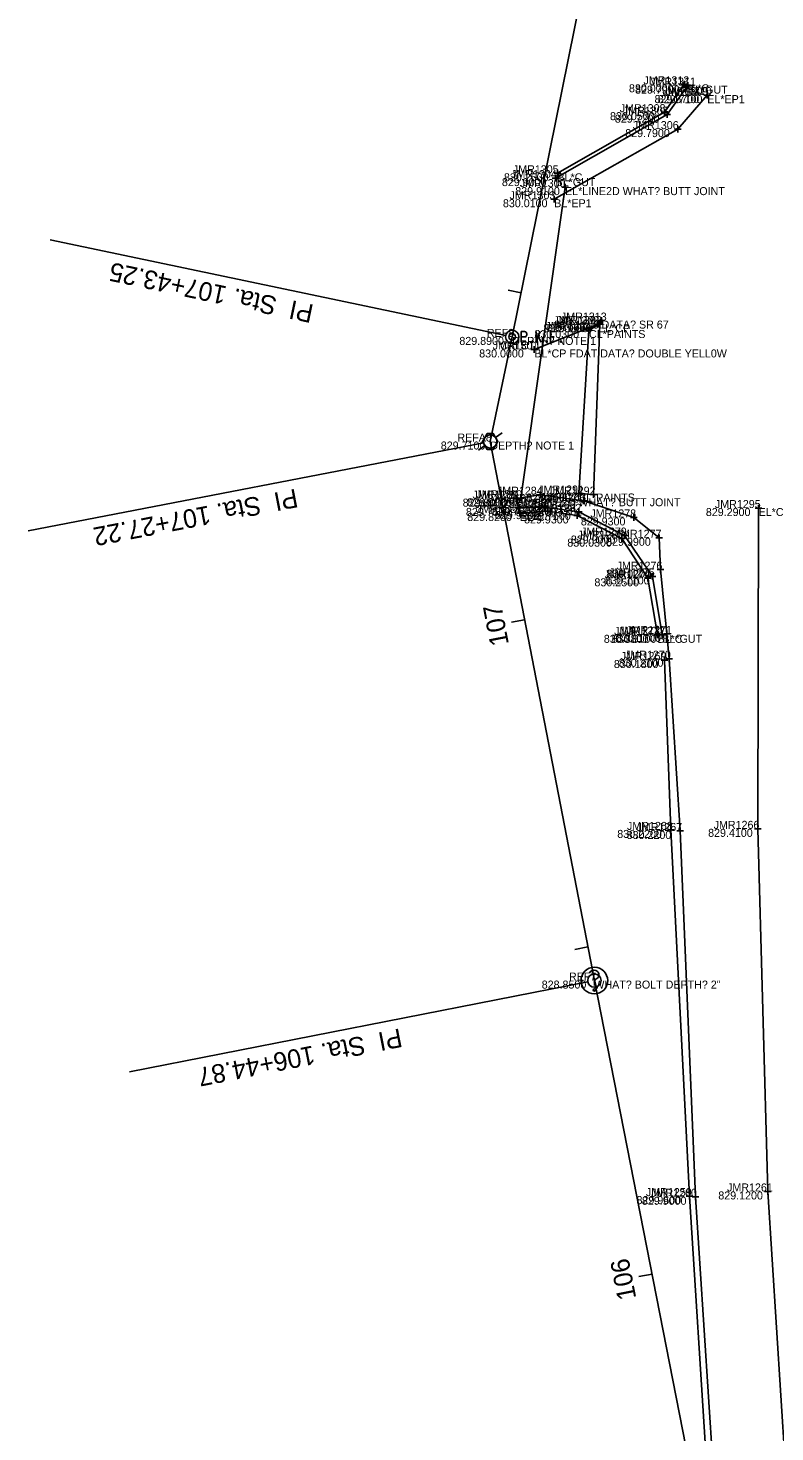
# Model space of a CAD drawing. Extents: x 1800057 to 1804439, y 483822 to 495007.
# Drawn here: x 1800057 to 1800169.1, y 493615 to 493825.6 of the extents above; entities that cross this region are included whole.
import ezdxf

# ---------------------------------------------------------------- set-up
doc = ezdxf.new("R2010")
doc.units = 0
for name, color, linetype in [('Default', 7, 'Continuous'), ('PM_X_Stop_Line', 7, 'Continuous'), ('PV_X_Curb', 7, 'Continuous'), ('PV_X_EOP', 7, 'Continuous'), ('PV_X_Shoulder', 7, 'Continuous'), ('RD_X_Misc_Items', 7, 'Continuous'), ('SV_X_Center_of_Pavt', 7, 'Continuous'), ('SV_X_CL_Survey_20', 7, 'Continuous'), ('SV_X_Control_Cells_Found', 7, 'Continuous'), ('SV_X_Shot_Marker', 7, 'Continuous'), ('SV_X_Text_Comment', 7, 'Continuous'), ('SV_X_Text_Elevation', 7, 'Continuous'), ('SV_X_Text_Name', 7, 'Continuous')]:
    doc.layers.add(name, color=color, linetype=linetype)

msp = doc.modelspace()

# ---------------------------------------------------------------- linework, layer by layer
at = {"layer": 'Default'}
msp.add_line((1800130.91, 493755.03), (1800137.56, 493801.7), dxfattribs=at)
at = {"layer": 'PM_X_Stop_Line'}
msp.add_lwpolyline([(1800139.65, 493755.74), (1800141.82, 493755.57), (1800142.77, 493781.15), (1800141.15, 493780.26), (1800139.65, 493755.74)], dxfattribs=at)
at = {"layer": 'PV_X_Curb'}
for points in [[(1800136.14, 493803.05), (1800152.91, 493812.57), (1800155.99, 493816.92)], [(1800136.42, 493803.77), (1800152.47, 493812.94), (1800155.42, 493817.12)], [(1800152.16, 493734.55), (1800150.67, 493743.31), (1800146.48, 493749.43), (1800139.65, 493752.99), (1800134.5, 493753.68), (1800130.59, 493753.58)], [(1800151.44, 493734.54), (1800150, 493743.02), (1800146.08, 493748.97), (1800139.36, 493752.45), (1800134.96, 493753.1), (1800130.78, 493752.81)]]:
    msp.add_lwpolyline(points, dxfattribs=at)
at = {"layer": 'PV_X_EOP'}
for points in [[(1800135.93, 493799.88), (1800154.5, 493810.4), (1800158.9, 493815.49)], [(1800458.51, 492019.19), (1800428.97, 492172.53), (1800371.73, 492460.04), (1800290.68, 492869.75), (1800235.42, 493149.26), (1800191.6, 493379.4), (1800183.7, 493423.96), (1800176.66, 493466.11), (1800169.82, 493511.65), (1800164.64, 493555.78), (1800160.38, 493600.77), (1800157.14, 493650.25), (1800154.83, 493705.12), (1800153.18, 493730.96), (1800152.82, 493734.69), (1800151.9, 493744.32), (1800151.68, 493749.1), (1800147.88, 493752.15), (1800140.39, 493754.62), (1800133.87, 493755.56), (1800130.23, 493754.97)]]:
    msp.add_lwpolyline(points, dxfattribs=at)
at = {"layer": 'PV_X_Shoulder'}
msp.add_lwpolyline([(1800457.45, 492018.92), (1800428.43, 492172.5), (1800370.8, 492459.92), (1800289.79, 492869.77), (1800234.57, 493149.05), (1800190.93, 493379.44), (1800182.91, 493423.69), (1800175.76, 493466.05), (1800168.8, 493511.21), (1800163.57, 493555.93), (1800159.41, 493600.52), (1800156.25, 493650.35), (1800153.42, 493705.28), (1800152.47, 493730.76)], dxfattribs=at)
at = {"layer": 'RD_X_Misc_Items'}
msp.add_line((1800141.96, 493681.92), (1800141.96, 493682.4), dxfattribs=at)
for centre, radius in [((1800141.96, 493682.68), 2), ((1800141.96, 493681.27), 0.17)]:
    msp.add_circle(centre, radius, dxfattribs=at)
for centre, radius, start, end in [((1800141.89, 493683.49), 0.754, 88.324, 152.5385), ((1800141.95, 493683.56), 0.688, 291.9329, 92.4584), ((1800142.54, 493682.44), 0.587, 125.4618, 184.0829)]:
    msp.add_arc(centre, radius, start, end, dxfattribs=at)
at = {"layer": 'SV_X_Center_of_Pavt'}
msp.add_line((1800132.95, 493777.35), (1800142.51, 493781.14), dxfattribs=at)
msp.add_lwpolyline([(1800469.01, 492021.22), (1800439.37, 492174.81), (1800382.15, 492462.11), (1800301, 492872.15), (1800245.93, 493151.03), (1800202.07, 493381.28), (1800193.97, 493425.46), (1800186.87, 493467.92), (1800180.32, 493514.37), (1800175.39, 493555.88), (1800171.19, 493600.63), (1800167.99, 493651.05), (1800166.49, 493705.44), (1800166.61, 493753.56)], dxfattribs=at)
at = {"layer": 'SV_X_CL_Survey_20'}
for p, q in [((1800129.64, 493779.23), (1800291.16, 494582.06)), ((1800129.64, 493779.23), (1800291.16, 494582.06)), ((1800128.66, 493779.43), (1800060.32, 493793.81)), ((1800130.97, 493785.84), (1800129.01, 493786.24)), ((1800126.34, 493763.54), (1800129.64, 493779.23)), ((1800126.34, 493763.54), (1800129.64, 493779.23)), ((1800125.36, 493763.35), (1800056.98, 493750.15)), ((1800141.96, 493682.68), (1800126.34, 493763.54)), ((1800141.96, 493682.68), (1800126.34, 493763.54)), ((1800131.5, 493736.81), (1800129.54, 493736.43)), ((1800140.98, 493687.72), (1800139.02, 493687.34)), ((1800140.98, 493682.49), (1800072.21, 493668.97)), ((1800325.88, 492747.04), (1800141.96, 493682.68)), ((1800325.88, 492747.04), (1800141.96, 493682.68)), ((1800150.61, 493638.66), (1800148.65, 493638.27))]:
    msp.add_line(p, q, dxfattribs=at)
for centre in [(1800129.64, 493779.23), (1800126.34, 493763.54), (1800141.96, 493682.68)]:
    msp.add_circle(centre, 1, dxfattribs=at)
at = {"layer": 'SV_X_Control_Cells_Found'}
for p, q in [((1800128.11, 493764.86), (1800127.14, 493764.14)), ((1800125.53, 493762.94), (1800124.57, 493762.22))]:
    msp.add_line(p, q, dxfattribs=at)
for points in [[(1800131, 493778.43), (1800131, 493780.03), (1800131.53, 493780.03), (1800131.58, 493780.01), (1800131.66, 493779.99), (1800131.69, 493779.96), (1800131.73, 493779.94), (1800131.77, 493779.87), (1800131.8, 493779.81), (1800131.83, 493779.71), (1800131.83, 493779.56), (1800131.81, 493779.51), (1800131.79, 493779.43), (1800131.75, 493779.34), (1800131.7, 493779.31), (1800131.67, 493779.28), (1800131.62, 493779.26), (1800131.53, 493779.24), (1800131, 493779.24)], [(1800132.64, 493778.64), (1800132.7, 493778.64), (1800132.73, 493778.61), (1800132.76, 493778.56), (1800132.76, 493778.5), (1800132.73, 493778.45), (1800132.7, 493778.43), (1800132.64, 493778.43), (1800132.61, 493778.45), (1800132.58, 493778.5), (1800132.58, 493778.56), (1800132.61, 493778.61), (1800132.64, 493778.64)], [(1800133.25, 493780.03), (1800133.25, 493778.43)], [(1800133.89, 493780.03), (1800133.25, 493779)], [(1800133.46, 493779.33), (1800134, 493778.43)], [(1800134.78, 493778.64), (1800134.84, 493778.64), (1800134.87, 493778.61), (1800134.9, 493778.56), (1800134.9, 493778.5), (1800134.87, 493778.45), (1800134.84, 493778.43), (1800134.78, 493778.43), (1800134.75, 493778.45), (1800134.71, 493778.5), (1800134.71, 493778.56), (1800134.75, 493778.61), (1800134.78, 493778.64)], [(1800136.15, 493780.03), (1800135.39, 493780.03), (1800135.39, 493778.43)], [(1800135.39, 493779.24), (1800135.93, 493779.24)], [(1800136.93, 493778.64), (1800136.98, 493778.64), (1800137.02, 493778.61), (1800137.05, 493778.56), (1800137.05, 493778.5), (1800137.02, 493778.45), (1800136.98, 493778.43), (1800136.93, 493778.43), (1800136.9, 493778.45), (1800136.86, 493778.5), (1800136.86, 493778.56), (1800136.9, 493778.61), (1800136.93, 493778.64)]]:
    msp.add_lwpolyline(points, dxfattribs=at)
msp.add_lwpolyline([(1800125.89, 493764.74), (1800126.79, 493764.74), (1800127.5, 493763.54), (1800126.79, 493762.34), (1800125.89, 493762.34), (1800125.18, 493763.54)], close=True, dxfattribs=at)
msp.add_circle((1800129.64, 493779.23), 0.497, dxfattribs=at)
at = {"layer": 'SV_X_Shot_Marker'}
for p, q in [((1800154.92, 493817.12), (1800155.92, 493817.12)), ((1800155.42, 493817.62), (1800155.42, 493816.62)), ((1800155.42, 493817.12), (1800155.42, 493817.12)), ((1800155.49, 493816.92), (1800156.49, 493816.92)), ((1800155.99, 493817.42), (1800155.99, 493816.42)), ((1800155.99, 493816.92), (1800155.99, 493816.92)), ((1800158.9, 493815.99), (1800158.9, 493814.99)), ((1800158.91, 493816), (1800158.91, 493815)), ((1800158.4, 493815.49), (1800159.4, 493815.49)), ((1800158.41, 493815.5), (1800159.41, 493815.5)), ((1800158.9, 493815.49), (1800158.9, 493815.49)), ((1800158.91, 493815.5), (1800158.91, 493815.5)), ((1800151.97, 493812.94), (1800152.97, 493812.94)), ((1800152.41, 493812.57), (1800153.41, 493812.57)), ((1800152.47, 493813.44), (1800152.47, 493812.44)), ((1800152.47, 493812.94), (1800152.47, 493812.94)), ((1800152.91, 493813.07), (1800152.91, 493812.07)), ((1800152.91, 493812.57), (1800152.91, 493812.57)), ((1800154, 493810.4), (1800155, 493810.4)), ((1800154.5, 493810.9), (1800154.5, 493809.9)), ((1800154.5, 493810.4), (1800154.5, 493810.4)), ((1800135.92, 493803.77), (1800136.92, 493803.77)), ((1800136.14, 493803.55), (1800136.14, 493802.55)), ((1800136.42, 493804.27), (1800136.42, 493803.27)), ((1800136.42, 493803.77), (1800136.42, 493803.77)), ((1800135.64, 493803.05), (1800136.64, 493803.05)), ((1800136.14, 493803.05), (1800136.14, 493803.05)), ((1800137.06, 493801.7), (1800138.06, 493801.7)), ((1800137.56, 493802.2), (1800137.56, 493801.2)), ((1800137.56, 493801.7), (1800137.56, 493801.7)), ((1800135.43, 493799.88), (1800136.43, 493799.88)), ((1800135.93, 493800.38), (1800135.93, 493799.38)), ((1800135.93, 493799.88), (1800135.93, 493799.88)), ((1800140.65, 493780.26), (1800141.65, 493780.26)), ((1800141.15, 493780.76), (1800141.15, 493779.76)), ((1800141.15, 493780.26), (1800141.15, 493780.26)), ((1800142.01, 493781.14), (1800143.01, 493781.14)), ((1800142.27, 493781.15), (1800143.27, 493781.15)), ((1800142.51, 493781.64), (1800142.51, 493780.64)), ((1800142.51, 493781.14), (1800142.51, 493781.14)), ((1800142.54, 493781.68), (1800143.54, 493781.68)), ((1800142.77, 493781.65), (1800142.77, 493780.65)), ((1800142.77, 493781.15), (1800142.77, 493781.15)), ((1800143.04, 493782.18), (1800143.04, 493781.18)), ((1800143.04, 493781.68), (1800143.04, 493781.68)), ((1800132.45, 493777.35), (1800133.45, 493777.35)), ((1800132.45, 493777.35), (1800133.45, 493777.35)), ((1800132.95, 493777.85), (1800132.95, 493776.85)), ((1800132.95, 493777.85), (1800132.95, 493776.85)), ((1800132.95, 493777.35), (1800132.95, 493777.35)), ((1800132.95, 493777.35), (1800132.95, 493777.35)), ((1800129.73, 493754.97), (1800130.73, 493754.97)), ((1800130.23, 493755.47), (1800130.23, 493754.47)), ((1800130.23, 493754.97), (1800130.23, 493754.97)), ((1800130.41, 493755.03), (1800131.41, 493755.03)), ((1800130.91, 493755.53), (1800130.91, 493754.53)), ((1800130.91, 493755.03), (1800130.91, 493755.03)), ((1800133.37, 493755.56), (1800134.37, 493755.56)), ((1800133.87, 493756.06), (1800133.87, 493755.06)), ((1800133.87, 493755.56), (1800133.87, 493755.56)), ((1800139.15, 493755.74), (1800140.15, 493755.74)), ((1800139.65, 493756.24), (1800139.65, 493755.24)), ((1800139.65, 493755.74), (1800139.65, 493755.74)), ((1800140.39, 493755.12), (1800140.39, 493754.12)), ((1800141.32, 493755.57), (1800142.32, 493755.57)), ((1800141.82, 493756.07), (1800141.82, 493755.07)), ((1800141.82, 493755.57), (1800141.82, 493755.57)), ((1800130.09, 493753.58), (1800131.09, 493753.58)), ((1800130.28, 493752.81), (1800131.28, 493752.81)), ((1800130.59, 493754.08), (1800130.59, 493753.08)), ((1800130.59, 493753.58), (1800130.59, 493753.58)), ((1800130.78, 493753.31), (1800130.78, 493752.31)), ((1800130.78, 493752.81), (1800130.78, 493752.81)), ((1800134, 493753.68), (1800135, 493753.68)), ((1800134.46, 493753.1), (1800135.46, 493753.1)), ((1800134.5, 493754.18), (1800134.5, 493753.18)), ((1800134.5, 493753.68), (1800134.5, 493753.68)), ((1800134.96, 493753.6), (1800134.96, 493752.6)), ((1800134.96, 493753.1), (1800134.96, 493753.1)), ((1800139.15, 493752.99), (1800140.15, 493752.99)), ((1800139.36, 493752.95), (1800139.36, 493751.95)), ((1800139.65, 493753.49), (1800139.65, 493752.49)), ((1800139.65, 493752.99), (1800139.65, 493752.99)), ((1800139.89, 493754.62), (1800140.89, 493754.62)), ((1800140.39, 493754.62), (1800140.39, 493754.62)), ((1800166.11, 493753.56), (1800167.11, 493753.56)), ((1800166.61, 493754.06), (1800166.61, 493753.06)), ((1800166.61, 493753.56), (1800166.61, 493753.56)), ((1800138.86, 493752.45), (1800139.86, 493752.45)), ((1800139.36, 493752.45), (1800139.36, 493752.45)), ((1800147.38, 493752.15), (1800148.38, 493752.15)), ((1800147.88, 493752.65), (1800147.88, 493751.65)), ((1800147.88, 493752.15), (1800147.88, 493752.15)), ((1800145.58, 493748.97), (1800146.58, 493748.97)), ((1800145.98, 493749.43), (1800146.98, 493749.43)), ((1800146.08, 493749.47), (1800146.08, 493748.47)), ((1800146.08, 493748.97), (1800146.08, 493748.97)), ((1800146.48, 493749.93), (1800146.48, 493748.93)), ((1800146.48, 493749.43), (1800146.48, 493749.43)), ((1800151.18, 493749.1), (1800152.18, 493749.1)), ((1800151.68, 493749.6), (1800151.68, 493748.6)), ((1800151.68, 493749.1), (1800151.68, 493749.1)), ((1800151.9, 493744.82), (1800151.9, 493743.82)), ((1800149.5, 493743.02), (1800150.5, 493743.02)), ((1800150, 493743.52), (1800150, 493742.52)), ((1800150, 493743.02), (1800150, 493743.02)), ((1800150.17, 493743.31), (1800151.17, 493743.31)), ((1800150.67, 493743.81), (1800150.67, 493742.81)), ((1800150.67, 493743.31), (1800150.67, 493743.31)), ((1800151.4, 493744.32), (1800152.4, 493744.32)), ((1800151.9, 493744.32), (1800151.9, 493744.32)), ((1800150.94, 493734.54), (1800151.94, 493734.54)), ((1800151.44, 493735.04), (1800151.44, 493734.04)), ((1800151.44, 493734.54), (1800151.44, 493734.54)), ((1800151.66, 493734.55), (1800152.66, 493734.55)), ((1800152.16, 493735.05), (1800152.16, 493734.05)), ((1800152.16, 493734.55), (1800152.16, 493734.55)), ((1800152.32, 493734.69), (1800153.32, 493734.69)), ((1800152.82, 493735.19), (1800152.82, 493734.19)), ((1800152.82, 493734.69), (1800152.82, 493734.69)), ((1800151.97, 493730.76), (1800152.97, 493730.76)), ((1800152.47, 493731.26), (1800152.47, 493730.26)), ((1800152.47, 493730.76), (1800152.47, 493730.76)), ((1800152.68, 493730.96), (1800153.68, 493730.96)), ((1800153.18, 493731.46), (1800153.18, 493730.46)), ((1800153.18, 493730.96), (1800153.18, 493730.96)), ((1800152.92, 493705.28), (1800153.92, 493705.28)), ((1800153.42, 493705.78), (1800153.42, 493704.78)), ((1800153.42, 493705.28), (1800153.42, 493705.28)), ((1800154.33, 493705.12), (1800155.33, 493705.12)), ((1800154.83, 493705.62), (1800154.83, 493704.62)), ((1800154.83, 493705.12), (1800154.83, 493705.12)), ((1800165.99, 493705.44), (1800166.99, 493705.44)), ((1800166.49, 493705.94), (1800166.49, 493704.94)), ((1800166.49, 493705.44), (1800166.49, 493705.44)), ((1800155.75, 493650.35), (1800156.75, 493650.35)), ((1800156.25, 493650.85), (1800156.25, 493649.85)), ((1800156.25, 493650.35), (1800156.25, 493650.35)), ((1800156.64, 493650.25), (1800157.64, 493650.25)), ((1800157.14, 493650.75), (1800157.14, 493649.75)), ((1800157.14, 493650.25), (1800157.14, 493650.25)), ((1800167.49, 493651.05), (1800168.49, 493651.05)), ((1800167.99, 493651.55), (1800167.99, 493650.55)), ((1800167.99, 493651.05), (1800167.99, 493651.05))]:
    msp.add_line(p, q, dxfattribs=at)

# ---------------------------------------------------------------- texts
at = {"layer": 'SV_X_CL_Survey_20'}
for s, rotation, p in [('PI  Sta. 107+43.25', 168.1206, (1800099.99, 493784.03)), ('PI  Sta. 107+27.22', 190.9321, (1800097.15, 493756.48)), ('107', 100.9321, (1800129.15, 493733.16)), ('PI  Sta. 106+44.87', 191.1211, (1800112.79, 493675.52)), ('106', 101.1211, (1800148.26, 493635.05))]:
    msp.add_text(s, height=2.8, rotation=rotation, dxfattribs=at).set_placement(p)
at = {"layer": 'SV_X_Text_Comment'}
for s, p in [('EL*C', (1800155.42, 493815.92)), ('EL*GUT', (1800155.99, 493815.72)), ('EL*EP1', (1800158.9, 493814.29)), ('EL*EP1', (1800158.91, 493814.3)), ('BL*C', (1800136.42, 493802.57)), ('BL*GUT', (1800136.14, 493801.85)), ('EL*LINE2D WHAT? BUTT JOINT', (1800137.56, 493800.5)), ('BL*EP1', (1800135.93, 493798.68)), ('CL*PAINTS', (1800141.15, 493779.06)), ('EL*CP', (1800142.51, 493779.94)), ('DATA? SR 67', (1800143.04, 493780.48)), ('DEPTH? NOTE 1', (1800129.64, 493778.03)), ('BL*CP FDAT DATA? DOUBLE YELL0W', (1800132.95, 493776.15)), ('DEPTH? NOTE 1', (1800126.34, 493762.34)), ('EL*EP1', (1800130.23, 493753.77)), ('BL*LINE2D WHAT? BUTT JOINT', (1800130.91, 493753.83)), ('BL*PAINTS', (1800139.65, 493754.54)), ('EL*GUT', (1800130.59, 493752.38)), ('EL*C', (1800130.78, 493751.61)), ('EL*CP', (1800166.61, 493752.36)), ('BL*C', (1800151.44, 493733.34)), ('BL*GUT', (1800152.16, 493733.35)), ('WHAT? BOLT DEPTH? 2"', (1800141.96, 493681.48))]:
    msp.add_text(s, height=1.2, dxfattribs=at).set_placement(p)
at = {"layer": 'SV_X_Text_Elevation'}
for s, p in [('830.0000', (1800147.15, 493815.92)), ('829.7900', (1800148.07, 493815.72)), ('829.6700', (1800150.99, 493814.3)), ('829.7100', (1800151.48, 493814.29)), ('830.0500', (1800144.31, 493811.74)), ('829.7200', (1800145.03, 493811.37)), ('829.7900', (1800146.59, 493809.2)), ('830.2500', (1800128.39, 493802.57)), ('829.9000', (1800128.09, 493801.85)), ('829.9100', (1800130.09, 493800.5)), ('830.0100', (1800128.24, 493798.68)), ('830.0300', (1800132.97, 493779.06)), ('830.0300', (1800134.32, 493779.94)), ('829.9900', (1800134.82, 493779.95)), ('830.1100', (1800135.94, 493780.48)), ('829.8900', (1800121.7, 493778.03)), ('830.0000', (1800124.68, 493776.15)), ('830.0000', (1800124.68, 493776.15)), ('829.7100', (1800118.91, 493762.34)), ('829.8000', (1800122.2, 493753.77)), ('829.8000', (1800122.88, 493753.83)), ('829.8500', (1800125.95, 493754.36)), ('829.8600', (1800131.71, 493754.54)), ('829.8700', (1800133.92, 493754.37)), ('829.7500', (1800122.69, 493752.38)), ('829.8200', (1800122.89, 493751.61)), ('829.7500', (1800126.61, 493752.48)), ('829.9200', (1800127.04, 493751.9)), ('829.7600', (1800131.73, 493751.79)), ('829.8400', (1800132.47, 493753.42)), ('829.2900', (1800158.69, 493752.36)), ('829.9300', (1800131.41, 493751.25)), ('829.9300', (1800139.93, 493750.95)), ('830.0300', (1800137.9, 493747.77)), ('829.9000', (1800138.43, 493748.23)), ('829.9900', (1800143.73, 493747.9)), ('830.2500', (1800141.97, 493741.82)), ('830.1100', (1800143.56, 493742.11)), ('830.0200', (1800143.75, 493743.12)), ('830.3800', (1800143.38, 493733.34)), ('830.3100', (1800144.56, 493733.35)), ('830.1700', (1800145.26, 493733.49)), ('830.1800', (1800144.89, 493729.56)), ('830.2100', (1800145.63, 493729.76)), ('830.2200', (1800145.4, 493704.08)), ('830.2200', (1800146.81, 493703.92)), ('829.4100', (1800159.03, 493704.24)), ('828.8500', (1800134.06, 493681.48)), ('829.9600', (1800148.29, 493649.15)), ('829.9000', (1800149.09, 493649.05)), ('829.1200', (1800160.56, 493649.85))]:
    msp.add_text(s, height=1.2, dxfattribs=at).set_placement(p)
at = {"layer": 'SV_X_Text_Name'}
for s, p in [('JMR1312', (1800149.33, 493817.12)), ('JMR1311', (1800150.32, 493816.92)), ('JMR1309', (1800152.2, 493815.49)), ('JMR1310', (1800152.7, 493815.5)), ('JMR1308', (1800145.77, 493812.94)), ('JMR1307', (1800146.23, 493812.57)), ('JMR1306', (1800147.74, 493810.4)), ('JMR1304', (1800129.46, 493803.05)), ('JMR1305', (1800129.73, 493803.77)), ('JMR1300', (1800130.77, 493801.7)), ('JMR1303', (1800129.24, 493799.88)), ('JMR1302', (1800135.83, 493781.14)), ('JMR1293', (1800136.22, 493781.15)), ('JMR1313', (1800136.94, 493781.68)), ('REF8', (1800125.82, 493779.23)), ('JMR1294', (1800134.61, 493780.26)), ('JMR1301', (1800126.7, 493777.35)), ('CALC11', (1800127.82, 493777.35)), ('REFA8', (1800121.4, 493763.54)), ('JMR1289', (1800123.69, 493754.97)), ('JMR1290', (1800124.25, 493755.03)), ('JMR1284', (1800127.34, 493755.56)), ('JMR1291', (1800133.53, 493755.74)), ('JMR1283', (1800133.85, 493754.62)), ('JMR1292', (1800135.27, 493755.57)), ('JMR1288', (1800124.05, 493753.58)), ('JMR1287', (1800124.25, 493752.81)), ('JMR1285', (1800127.97, 493753.68)), ('JMR1286', (1800128.35, 493753.1)), ('JMR1282', (1800133.12, 493752.99)), ('JMR1281', (1800133.26, 493752.45)), ('JMR1278', (1800141.36, 493752.15)), ('JMR1295', (1800160.05, 493753.56)), ('JMR1280', (1800139.44, 493748.97)), ('JMR1279', (1800139.95, 493749.43)), ('JMR1277', (1800145.16, 493749.1)), ('JMR1275', (1800144.15, 493743.31)), ('JMR1276', (1800145.3, 493744.32)), ('JMR1274', (1800143.5, 493743.02)), ('JMR1273', (1800144.93, 493734.54)), ('JMR1272', (1800145.65, 493734.55)), ('JMR1271', (1800146.74, 493734.69)), ('JMR1269', (1800145.9, 493730.76)), ('JMR1270', (1800146.56, 493730.96)), ('JMR1268', (1800146.85, 493705.28)), ('JMR1266', (1800159.86, 493705.44)), ('JMR1267', (1800148.27, 493705.12)), ('REF7', (1800138.15, 493682.68)), ('JMR1261', (1800161.87, 493651.05)), ('JMR1259', (1800149.7, 493650.35)), ('JMR1260', (1800150.48, 493650.25))]:
    msp.add_text(s, height=1.2, dxfattribs=at).set_placement(p)

doc.saveas('drawing.dxf')
